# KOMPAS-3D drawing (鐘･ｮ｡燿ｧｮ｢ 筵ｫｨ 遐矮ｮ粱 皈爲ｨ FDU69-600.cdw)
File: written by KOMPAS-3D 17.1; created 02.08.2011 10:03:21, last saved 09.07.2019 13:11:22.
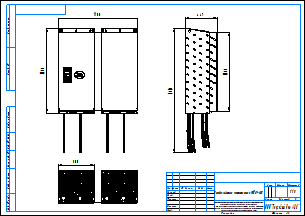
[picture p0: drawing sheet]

Title block, sheet 1: name: Преобразователи частоты серии FDU69-600; scale: 1:10; sheets: 1; sheet format: A3; stored path: \\adlc.lan\data\АДЛ_ПКД\3D-модели\Поставщики\Оборудование Emotron\Преобразователи частоты\Серия FDU 2.0\KOMPAS 2D\Преобразователи частоты серии FDU69-600.cdw

Views: Спереди 1
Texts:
  Рама для чертежей
  Лит-Масса-Масштаб
  Материал-Предприятие
  Масштаб
  Изм.
  Лист
  № докум.
  Подп.
  Дата
  Лит.
  Разраб.
  Пров.
  Т.контр.
  Листов
  Внимание! Данный продукт является объектом авторского права ООО «Торговый Дом АДЛ».
  Запрещается изменение, копирование, распространение
  (в том числе путем копирования на другие сайты и ресурсы в Интернете)
  или любое иное использование информации и объектов без предварительного
  согласия правообладателя (ООО «Торговый Дом АДЛ»).
  Н.контр.
  Утв.
  ООО "Торговый дом АДЛ"
  Изменение
  Номер документа
  Подпись
  Обозначение документа
  Наименование изделия
  Масса изделия по ГОСТ 2.109-73
  Порядковый номер листа
  Общее количество листов в документе
  Характер работы, выполненной лицом, подписавшим документ
  Наименование или индекс предприятия, выпускающего документ
  Инв. № подл.
  Подп. и дата
  Взам. инв. №
  Инв. № дубл.
  Инвентарный номер подлинника по ГОСТ 2.501-68
  Подпись принявшего подлинник в отдел технической документации
  Инвентарный номер подлинника, взамен которого выпущен данный подлинник
  Инвентарный номер дубликата по ГОСТ 2.502-68
  Подпись принявшего дубликат в отдел технической документации
  Справ. №
  Перв. примен.
  Обозначение документа, взамен или на основании которого выпущен данный документ
  Обозначение документа, в котором впервые записан данный документ
  Подпись лица, копировавшего чертеж
  Обозначение формата листа
  !Рама для чертежа
Dimensions and other numbers on the sheet: 1100; 1176; 449; 500; 1718; 1:10; 1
